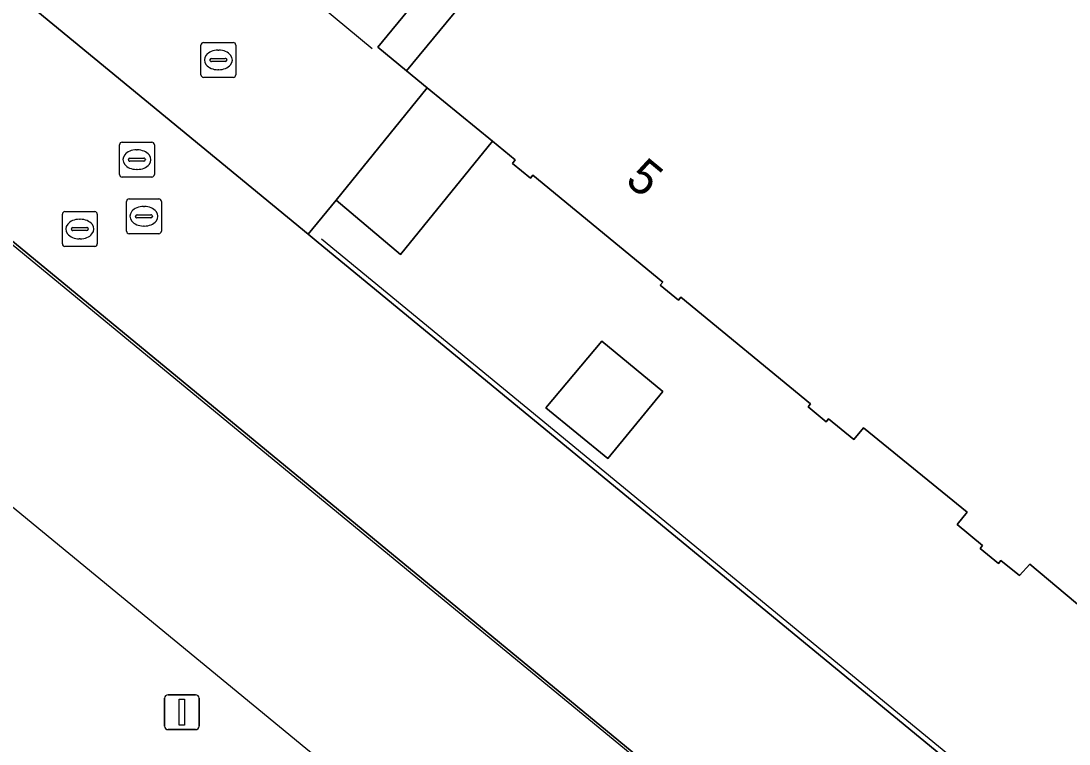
# Model space of a CAD drawing. Extents: x 161772 to 163126, y 383092 to 383917.
# Drawn here: x 162013.95 to 162044.01, y 383225.98 to 383246.72 of the extents above; entities that cross this region are included whole.
import ezdxf

# ---------------------------------------------------------------- set-up
doc = ezdxf.new("R2010")
doc.units = 0
for name, color, linetype in [('IMGEO_Erf', 7, 'Continuous'), ('IMGEO_Lage_trafo', 7, 'Continuous'), ('IMGEO_Lichtmast', 7, 'Continuous'), ('IMGEO_Lijnafwatering', 7, 'Continuous'), ('IMGEO_Pand', 7, 'Continuous'), ('IMGEO_Pand_nummerreeks', 7, 'Continuous'), ('IMGEO_Rijbaan_lokaal_open', 7, 'Continuous'), ('IMGEO_Rioolput', 7, 'Continuous'), ('IMGEO_Voetpad_gesloten', 7, 'Continuous')]:
    doc.layers.add(name, color=color, linetype=linetype)

msp = doc.modelspace()

# ---------------------------------------------------------------- linework, layer by layer
at = {"layer": 'IMGEO_Erf'}
for points in [[(162069.017, 383300.403), (162024.178, 383245.963), (162025.005, 383245.286), (162032.884, 383254.827)], [(162045.502, 383228.932), (162042.88, 383231.137), (162042.583, 383230.815), (162042.05, 383231.238), (162041.98, 383231.153), (162041.457, 383231.585), (162041.527, 383231.669), (162040.794, 383232.275), (162041.083, 383232.624), (162038.109, 383235.045), (162037.838, 383234.711), (162037.11, 383235.304), (162037.04, 383235.219), (162036.519, 383235.653), (162036.589, 383235.737), (162032.872, 383238.791), (162032.802, 383238.707), (162032.281, 383239.137), (162032.351, 383239.222), (162028.628, 383242.296), (162028.558, 383242.211), (162028.041, 383242.634), (162028.124, 383242.734), (162027.474, 383243.266), (162024.828, 383240.019), (162022.991, 383241.58), (162022.186, 383240.601), (162022.469, 383240.368), (162068.652, 383202.355)]]:
    msp.add_lwpolyline(points, dxfattribs=at)
msp.add_lwpolyline([(162030.775, 383234.169), (162029.004, 383235.624), (162030.604, 383237.53), (162032.356, 383236.092)], close=True, dxfattribs=at)
at = {"layer": 'IMGEO_Lage_trafo'}
msp.add_lwpolyline([(162029.004, 383235.624), (162030.775, 383234.169), (162032.356, 383236.092), (162030.604, 383237.53)], close=True, dxfattribs=at)
at = {"layer": 'IMGEO_Lichtmast'}
for p, q in [((162018.065, 383226.489), (162018.065, 383227.289)), ((162018.065, 383227.289), (162018.065, 383226.489)), ((162018.165, 383227.389), (162018.955, 383227.389)), ((162018.955, 383227.389), (162018.165, 383227.389)), ((162019.055, 383227.289), (162019.055, 383226.489)), ((162019.055, 383226.489), (162019.055, 383227.289)), ((162018.955, 383226.389), (162018.165, 383226.389)), ((162018.165, 383226.389), (162018.955, 383226.389))]:
    msp.add_line(p, q, dxfattribs=at)
msp.add_lwpolyline([(162018.485, 383227.264), (162018.635, 383227.264), (162018.635, 383226.514), (162018.485, 383226.514), (162018.485, 383227.264)], dxfattribs=at)
for centre, start, end in [((162018.165, 383227.289), 90, 180), ((162018.165, 383227.289), 90, 180), ((162018.955, 383227.289), 0, 90), ((162018.955, 383227.289), 360, 90), ((162018.165, 383226.489), 180, 270), ((162018.165, 383226.489), 180, 270), ((162018.955, 383226.489), 270, 0), ((162018.955, 383226.489), 270, 0)]:
    msp.add_arc(centre, 0.1, start, end, dxfattribs=at)
at = {"layer": 'IMGEO_Lijnafwatering'}
for points in [[(162024.024, 383245.919), (162014.415, 383253.897)], [(162011.215, 383242.341), (162025.331, 383230.723)], [(162004.142, 383240.642), (162019.092, 383228.343)], [(162022.563, 383240.47), (162038.819, 383227.104)], [(162025.331, 383230.723), (162039.447, 383219.105)], [(162019.092, 383228.343), (162034.042, 383216.044)], [(162038.819, 383227.104), (162055.076, 383213.739)]]:
    msp.add_lwpolyline(points, dxfattribs=at)
at = {"layer": 'IMGEO_Pand'}
msp.add_lwpolyline([(162032.884, 383254.827), (162025.005, 383245.286), (162025.594, 383244.804), (162027.474, 383243.266), (162028.124, 383242.734), (162028.041, 383242.634), (162028.558, 383242.211), (162028.628, 383242.296), (162032.351, 383239.222), (162032.281, 383239.137), (162032.802, 383238.707), (162032.872, 383238.791), (162036.589, 383235.737), (162036.519, 383235.653), (162037.04, 383235.219), (162037.11, 383235.304), (162037.838, 383234.711), (162038.109, 383235.045), (162041.083, 383232.624), (162040.794, 383232.275), (162041.527, 383231.669), (162041.457, 383231.585), (162041.98, 383231.153), (162042.05, 383231.238), (162042.583, 383230.815), (162042.88, 383231.137), (162045.502, 383228.932)], dxfattribs=at)
at = {"layer": 'IMGEO_Rijbaan_lokaal_open'}
for points in [[(161982.816, 383272.991), (162022.186, 383240.601), (162022.991, 383241.58), (162025.594, 383244.804), (162025.005, 383245.286), (162024.178, 383245.963), (162069.017, 383300.403)], [(162054.895, 383187.865), (162058.675, 383184.763), (162059.171, 383185.317), (162057.611, 383186.767), (162058.979, 383188.263), (162060.56, 383186.888), (162066.195, 383193.13), (162067.57, 383194.688), (162068.256, 383195.442), (161976.98, 383270.676), (161965.539, 383280.118), (161962.128, 383275.94), (161955.86, 383268.264), (161962.269, 383262.995), (161962.168, 383262.726), (161966.806, 383258.778), (161967.104, 383258.925), (161971.077, 383255.833), (162035.261, 383203.214), (162035.951, 383202.874)]]:
    msp.add_lwpolyline(points, dxfattribs=at)
msp.add_lwpolyline([(161982.816, 383272.991), (161980.385, 383274.991), (161956.7, 383294.535), (161953.358, 383290.171), (161965.539, 383280.118), (161976.98, 383270.676), (162068.256, 383195.442), (162072.024, 383199.58), (162068.652, 383202.355), (162022.469, 383240.368), (162022.186, 383240.601)], close=True, dxfattribs=at)
at = {"layer": 'IMGEO_Rioolput'}
for p, q in [((162019.108, 383245.174), (162019.108, 383246.026)), ((162019.183, 383246.1), (162020.035, 383246.1)), ((162020.109, 383246.026), (162020.109, 383245.174)), ((162019.41, 383245.643), (162019.808, 383245.643)), ((162019.596, 383245.88), (162019.621, 383245.88)), ((162019.367, 383245.594), (162019.367, 383245.606)), ((162019.805, 383245.557), (162019.407, 383245.557)), ((162019.851, 383245.606), (162019.851, 383245.594)), ((162020.035, 383245.1), (162019.183, 383245.1)), ((162019.619, 383245.32), (162019.594, 383245.32)), ((162016.846, 383243.24), (162017.698, 383243.24)), ((162016.771, 383242.314), (162016.771, 383243.166)), ((162017.259, 383243.02), (162017.284, 383243.02)), ((162017.772, 383243.166), (162017.772, 383242.314)), ((162017.03, 383242.734), (162017.03, 383242.746)), ((162017.468, 383242.697), (162017.07, 383242.697)), ((162017.073, 383242.783), (162017.471, 383242.783)), ((162017.514, 383242.746), (162017.514, 383242.734)), ((162017.282, 383242.46), (162017.257, 383242.46)), ((162017.698, 383242.24), (162016.846, 383242.24)), ((162016.974, 383240.69), (162016.974, 383241.542)), ((162017.049, 383241.616), (162017.901, 383241.616)), ((162017.975, 383241.542), (162017.975, 383240.69)), ((162015.134, 383240.323), (162015.134, 383241.175)), ((162015.209, 383241.249), (162016.061, 383241.249)), ((162016.135, 383241.175), (162016.135, 383240.323)), ((162017.233, 383241.11), (162017.233, 383241.122)), ((162017.276, 383241.159), (162017.674, 383241.159)), ((162017.462, 383241.396), (162017.487, 383241.396)), ((162017.717, 383241.122), (162017.717, 383241.11)), ((162015.622, 383241.029), (162015.647, 383241.029)), ((162017.671, 383241.073), (162017.273, 383241.073)), ((162017.485, 383240.836), (162017.46, 383240.836)), ((162015.393, 383240.743), (162015.393, 383240.755)), ((162015.831, 383240.706), (162015.433, 383240.706)), ((162015.436, 383240.792), (162015.834, 383240.792)), ((162015.877, 383240.755), (162015.877, 383240.743)), ((162017.901, 383240.616), (162017.049, 383240.616)), ((162016.061, 383240.249), (162015.209, 383240.249)), ((162015.645, 383240.469), (162015.62, 383240.469))]:
    msp.add_line(p, q, dxfattribs=at)
for points in [[(162019.108, 383245.174), (162019.108, 383246.026)], [(162019.183, 383246.1), (162020.035, 383246.1)], [(162020.109, 383246.026), (162020.109, 383245.174)], [(162020.035, 383245.1), (162019.183, 383245.1)], [(162016.846, 383243.24), (162017.698, 383243.24)], [(162016.771, 383242.314), (162016.771, 383243.166)], [(162017.772, 383243.166), (162017.772, 383242.314)], [(162017.698, 383242.24), (162016.846, 383242.24)], [(162016.974, 383240.69), (162016.974, 383241.542)], [(162017.049, 383241.616), (162017.901, 383241.616)], [(162017.975, 383241.542), (162017.975, 383240.69)], [(162015.134, 383240.323), (162015.134, 383241.175)], [(162015.209, 383241.249), (162016.061, 383241.249)], [(162016.135, 383241.175), (162016.135, 383240.323)], [(162017.901, 383240.616), (162017.049, 383240.616)], [(162016.061, 383240.249), (162015.209, 383240.249)]]:
    msp.add_lwpolyline(points, dxfattribs=at)
for centre, radius, start, end in [((162019.185, 383246.024), 0.0765, 91.552, 178.448), ((162019.185, 383246.024), 0.0765, 91.552, 178.448), ((162020.033, 383246.024), 0.0765, 1.552, 88.448), ((162020.033, 383246.024), 0.0765, 1.552, 88.448), ((162019.407, 383245.603), 0.0403, 85.8775, 175.7526), ((162019.812, 383245.605), 0.0386, 1.7309, 96.639), ((162019.404, 383245.593), 0.0366, 178.938, 274.7102), ((162019.808, 383245.6), 0.043, 264.8664, 352.4533), ((162019.185, 383245.176), 0.0765, 181.552, 268.448), ((162019.185, 383245.176), 0.0765, 181.552, 268.448), ((162020.033, 383245.176), 0.0765, 271.552, 358.448), ((162020.033, 383245.176), 0.0765, 271.552, 358.448), ((162016.848, 383243.164), 0.0765, 91.552, 178.448), ((162016.848, 383243.164), 0.0765, 91.552, 178.448), ((162017.696, 383243.164), 0.0765, 1.552, 88.448), ((162017.696, 383243.164), 0.0765, 1.552, 88.448), ((162017.07, 383242.743), 0.0403, 85.8775, 175.7526), ((162017.067, 383242.733), 0.0366, 178.938, 274.7102), ((162017.471, 383242.74), 0.043, 264.8664, 352.4533), ((162017.475, 383242.745), 0.0386, 1.7309, 96.639), ((162016.848, 383242.316), 0.0765, 181.552, 268.448), ((162016.848, 383242.316), 0.0765, 181.552, 268.448), ((162017.696, 383242.316), 0.0765, 271.552, 358.448), ((162017.696, 383242.316), 0.0765, 271.552, 358.448), ((162017.051, 383241.54), 0.0765, 91.552, 178.448), ((162017.051, 383241.54), 0.0765, 91.552, 178.448), ((162017.899, 383241.54), 0.0765, 1.552, 88.448), ((162017.899, 383241.54), 0.0765, 1.552, 88.448), ((162015.211, 383241.173), 0.0765, 91.552, 178.448), ((162015.211, 383241.173), 0.0765, 91.552, 178.448), ((162016.059, 383241.173), 0.0765, 1.552, 88.448), ((162016.059, 383241.173), 0.0765, 1.552, 88.448), ((162017.273, 383241.119), 0.0403, 85.8775, 175.7526), ((162017.678, 383241.121), 0.0386, 1.7309, 96.639), ((162017.27, 383241.109), 0.0366, 178.938, 274.7102), ((162017.674, 383241.116), 0.043, 264.8664, 352.4533), ((162015.433, 383240.752), 0.0403, 85.8775, 175.7526), ((162015.43, 383240.742), 0.0366, 178.938, 274.7102), ((162015.834, 383240.749), 0.043, 264.8664, 352.4533), ((162015.838, 383240.754), 0.0386, 1.7309, 96.639), ((162017.051, 383240.692), 0.0765, 181.552, 268.448), ((162017.051, 383240.692), 0.0765, 181.552, 268.448), ((162017.899, 383240.692), 0.0765, 271.552, 358.448), ((162017.899, 383240.692), 0.0765, 271.552, 358.448), ((162015.211, 383240.325), 0.0765, 181.552, 268.448), ((162015.211, 383240.325), 0.0765, 181.552, 268.448), ((162016.059, 383240.325), 0.0765, 271.552, 358.448), ((162016.059, 383240.325), 0.0765, 271.552, 358.448)]:
    msp.add_arc(centre, radius, start, end, dxfattribs=at)
for centre, major_axis, ratio, start_param, end_param in [((162019.595, 383245.6), (-0.387, 0.002), 0.722429, 4.712389, 7.853982), ((162019.62, 383245.6), (-0.39, 0.002), 0.717154, 1.570796, 4.712389), ((162017.258, 383242.74), (-0.387, 0.002), 0.722429, 4.712389, 7.853982), ((162017.283, 383242.74), (-0.39, 0.002), 0.717154, 1.570796, 4.712389), ((162017.461, 383241.116), (-0.387, 0.002), 0.722429, 4.712389, 7.853982), ((162017.486, 383241.116), (-0.39, 0.002), 0.717154, 1.570796, 4.712389), ((162015.621, 383240.749), (-0.387, 0.002), 0.722429, 4.712389, 7.853982), ((162015.646, 383240.749), (-0.39, 0.002), 0.717154, 1.570796, 4.712389)]:
    msp.add_ellipse(centre, major_axis=major_axis, ratio=ratio, start_param=start_param, end_param=end_param, dxfattribs=at)
at = {"layer": 'IMGEO_Voetpad_gesloten'}
msp.add_lwpolyline([(162027.474, 383243.266), (162025.594, 383244.804), (162022.991, 383241.58), (162024.828, 383240.019)], close=True, dxfattribs=at)

# ---------------------------------------------------------------- texts
at = {"layer": 'IMGEO_Pand_nummerreeks'}
msp.add_text('5', height=1, rotation=320.4545, dxfattribs=at).set_placement((162031.241, 383242.084))

doc.saveas('drawing.dxf')
